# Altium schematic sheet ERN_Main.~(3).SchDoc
size A; SheetNumber: 1; SheetTotal: 1; SPICEModelCacheDBTNACQE: <root> / <DocumentId>DBTNACQE</DocumentId> / <CacheFrame Number="0"> / <Model Name="1n5400" Kind="MDL"> / <Text>*1N5400 MCE / * 50V 3A Si Rectifier pkg:DO-201 1,2 / .MODEL 1N5400 D(IS=2.68E-12 RS=0.00977 N=1.17 TT=1.44E-5 CJO=1.24E-10 / + VJ=0.6 M=0.333 BV=66.6 IBV=1E-5 )</Text> / </Model> / </CacheFrame> / </root>
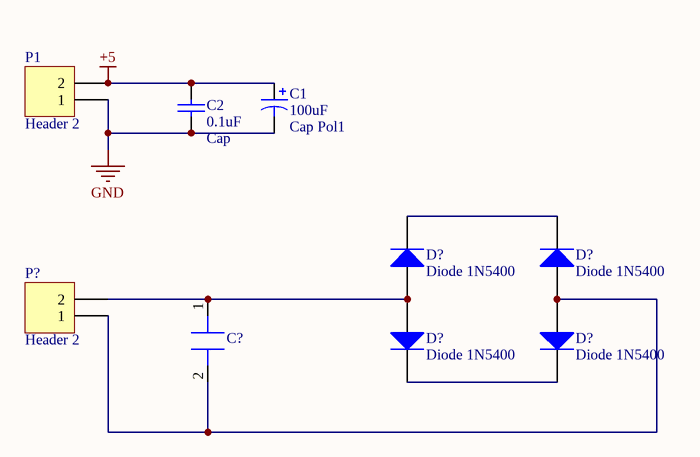
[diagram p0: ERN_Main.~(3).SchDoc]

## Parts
(Parts that share a designator on the sheet are numbered #1, #2 ... from top to bottom, then left to right.)
C1  Cap Pol1  value 100uF  [RB7.6-15]
C2  Cap  value 0.1uF  [RAD-0.3]
C?  C2220C944K5GLCAUTO  [CAPC5750X39M]  (value not drawn)
D?#1  Diode 1N5400  [DO-201AD]
D?#2  Diode 1N5400  [DO-201AD]
D?#3  Diode 1N5400  [DO-201AD]
D?#4  Diode 1N5400  [DO-201AD]
P1  Header 2  [HDR1X2]
P?  Header 2  [HDR1X2]

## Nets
+5: C1.1 C2.2 P1.2
GND: C1.2 C2.1 P1.1
NetC?_1: C?.1 D?#1.1(A) D?#3.1(A) P?.2
NetC?_2: C?.2 D?#2.1(A) D?#4.1(A) P?.1
NetD?#1_2: D?#1.2(K) D?#2.2(K)
NetD?#3_2: D?#3.2(K) D?#4.2(K)

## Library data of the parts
C1 = Cap Pol1: Polarized Capacitor (Radial)
C2 = Cap: Capacitor
C? = C2220C944K5GLCAUTO: CAP CER 0.94UF 50V C0G/NP0 2220
D?#1-D?#4 = Diode 1N5400: 3 Amp General Purpose Rectifier
P1 P? = Header 2: Header, 2-Pin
